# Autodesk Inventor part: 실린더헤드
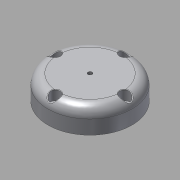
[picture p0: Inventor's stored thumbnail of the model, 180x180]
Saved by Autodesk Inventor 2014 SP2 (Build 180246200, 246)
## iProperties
Created: 2016-11
Part Number: 실린더헤드
Material: 알루미늄 6061
Document SubType Name: Modeling
Designer: mduedu
Density: 2.71 g/cm^3
Mass: 258.245 g
Surface Area: 216.96 cm^2
Volume: 95.2934 cm^3
Appearance: 알루미늄 - 평지
Author: mduedu
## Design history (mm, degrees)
sketch "스케치1"
  geometry: C1 r 42 at (0, 0); 1 further point
  constraints: 1 centre point, 1 coincident
  dimensions: "d0" = 84 diameter of C1
extrude "돌출1" new body sketch "스케치1" distance "d1" = 24; taper "d2" = 0 deg
fillet "모깎기1" dims "d3" = 10
sketch "스케치2"
  geometry: C1 r 30 at (0, 0); 1 further point
  constraints: 1 centre point, 1 coincident
  dimensions: "d4" = 60 diameter of C1
extrude "돌출2" join sketch "스케치2" distance "d5" = 5; taper "d6" = 0 deg
sketch "스케치3"
  geometry: C1 r 25 at (0, 0); 1 further point
  constraints: 1 centre point, 1 coincident
  dimensions: "d7" = 50 diameter of C1
extrude "돌출3" cut sketch "스케치3" distance "d8" = 20; taper "d9" = 0 deg
hole "구멍1" diameter "d12" = 4.134; stored, may be unused: countersink angle "d16" = 90 deg, drill point angle "d18" = 118 deg; dims "d10" = 10, "d11" = 10, "d13" = 6, "d14" = 4, "d15" = 2, "d17" = 8
chamfer "모따기1" distance "d19" = 1; stored, may be unused: second distance "d20" = 2, angle "d21" = 45 deg
fillet "모깎기2" dims "d22" = 3
sketch "스케치4"
  geometry: C1 r 17.5 at (0, 0); 1 further point
  constraints: 1 centre point, 1 coincident
  dimensions: "d23" = 35 diameter of C1
extrude "돌출4" cut sketch "스케치4" distance "d24" = 2; taper "d25" = 0 deg
fillet "모깎기3" dims "d26" = 0.5
sketch "스케치5" dims "d32" = 70
  geometry: C1 r 5 at (0, 35); 3 further points
  constraints: 2 coincident, 2 vertical alignment, 1 centre point, 2 other
  dimensions: "d33" = 10 diameter of C1
extrude "돌출5" cut sketch "스케치5" distance "d34" = 10; taper "d35" = 0 deg
sketch "스케치6" dims "d39" = 70
  geometry: 6 further points
  constraints: 2 vertical alignment, 1 coincident, 7 other
  dimensions: "d42" = 360 deg dimension on point (0, -35) point (0, 0) (derived)
sketch "스케치7"
  geometry: 4 further points
  constraints: 4 other
hole "구멍2" sketch "스케치7" at (0, 70), (-35, 35), (35, 35), (0, 0) diameter "d44" = 5.5; stored, may be unused: countersink angle "d48" = 90 deg, drill point angle "d50" = 0 deg; dims "d45" = 6, "d46" = 4, "d47" = 2, "d49" = 8
fillet "모깎기4" dims "d51" = 0.5
chamfer "모따기2" distance "d54" = 5; stored, may be unused: second distance "d55" = 2, angle "d56" = 30 deg
node "솔리드1"
pattern_circular "원형 패턴1" dims angle "d37" = 360 deg
